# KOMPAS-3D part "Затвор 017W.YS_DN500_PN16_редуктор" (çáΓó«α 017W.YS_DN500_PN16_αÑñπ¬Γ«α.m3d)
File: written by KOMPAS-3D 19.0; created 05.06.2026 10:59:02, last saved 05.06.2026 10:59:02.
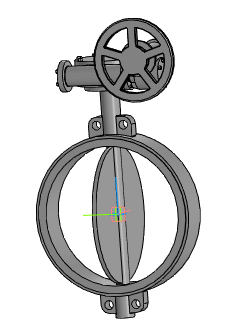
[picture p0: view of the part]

Document properties: Автор: Энергия; Полное имя файла: ..\..\..\3d для проектировщиков\x.x Тип 017W.Y(S) Затвор дисковый поворотный межфланцевый\Затвор 017W.Y(S)_DN50-DN1200_редуктор\Затвор 017W.YS_DN500_PN16_редуктор.a3d

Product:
- Part/product: Затвор 017W.YS_DN500_PN16_редуктор
    Масса: 165.721

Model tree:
1. Операция без истории:1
